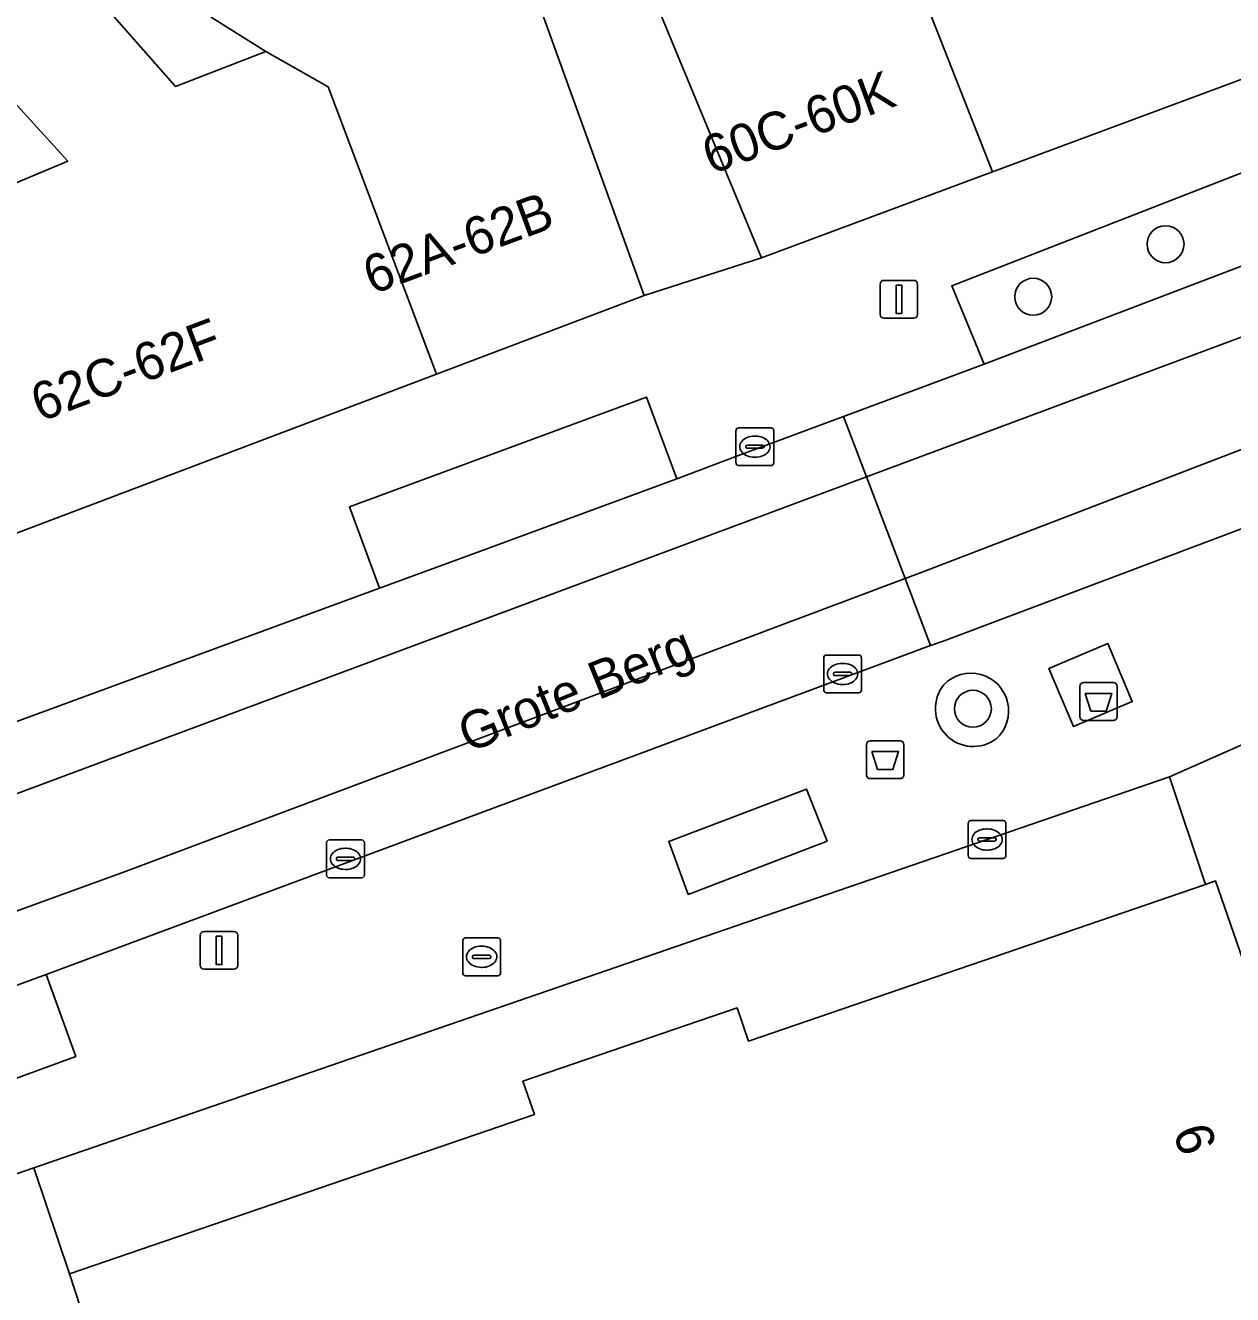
# Model space of a CAD drawing. Extents: x 160663 to 161506, y 382245 to 383291.
# Drawn here: x 161109.73 to 161141.68, y 382936.36 to 382969.94 of the extents above; entities that cross this region are included whole.
import ezdxf

# ---------------------------------------------------------------- set-up
doc = ezdxf.new("R2010")
doc.units = 0
for name, color, linetype in [('IMGEO_Afval_apart_plaats', 7, 'Continuous'), ('IMGEO_Afvalbak', 7, 'Continuous'), ('IMGEO_Boom', 7, 'Continuous'), ('IMGEO_Brandkraan', 7, 'Continuous'), ('IMGEO_Erf', 7, 'Continuous'), ('IMGEO_Groenvoorziening', 7, 'Continuous'), ('IMGEO_Kolk', 7, 'Continuous'), ('IMGEO_Lichtmast', 7, 'Continuous'), ('IMGEO_Openbare_ruimte_label', 7, 'Continuous'), ('IMGEO_Pand', 7, 'Continuous'), ('IMGEO_Pand_nummerreeks', 7, 'Continuous'), ('IMGEO_Rijbaan_lokaal_gesloten', 7, 'Continuous'), ('IMGEO_Voetpad_gesloten', 7, 'Continuous'), ('IMGEO_Voetpad_open', 7, 'Continuous')]:
    doc.layers.add(name, color=color, linetype=linetype)

msp = doc.modelspace()

# ---------------------------------------------------------------- linework, layer by layer
at = {"layer": 'IMGEO_Afval_apart_plaats'}
for p, q in [((161137.732, 382952.553), (161138.522, 382952.553)), ((161138.522, 382952.553), (161137.732, 382952.553)), ((161137.632, 382951.653), (161137.632, 382952.453)), ((161137.632, 382952.453), (161137.632, 382951.653)), ((161138.622, 382952.453), (161138.622, 382951.653)), ((161138.622, 382951.653), (161138.622, 382952.453)), ((161138.522, 382951.553), (161137.732, 382951.553)), ((161137.732, 382951.553), (161138.522, 382951.553))]:
    msp.add_line(p, q, dxfattribs=at)
msp.add_lwpolyline([(161137.775, 382952.267), (161138.479, 382952.267), (161138.33, 382951.797), (161137.924, 382951.797), (161137.775, 382952.267)], dxfattribs=at)
for centre, start, end in [((161137.732, 382952.453), 90, 180), ((161137.732, 382952.453), 90, 180), ((161138.522, 382952.453), 0, 90), ((161138.522, 382952.453), 360, 90), ((161137.732, 382951.653), 180, 270), ((161137.732, 382951.653), 180, 270), ((161138.522, 382951.653), 270, 0), ((161138.522, 382951.653), 270, 0)]:
    msp.add_arc(centre, 0.1, start, end, dxfattribs=at)
at = {"layer": 'IMGEO_Afvalbak'}
for p, q in [((161131.988, 382950.111), (161131.988, 382950.911)), ((161131.988, 382950.911), (161131.988, 382950.111)), ((161132.088, 382951.011), (161132.878, 382951.011)), ((161132.878, 382951.011), (161132.088, 382951.011)), ((161132.978, 382950.911), (161132.978, 382950.111)), ((161132.978, 382950.111), (161132.978, 382950.911)), ((161132.878, 382950.011), (161132.088, 382950.011)), ((161132.088, 382950.011), (161132.878, 382950.011))]:
    msp.add_line(p, q, dxfattribs=at)
msp.add_lwpolyline([(161132.131, 382950.725), (161132.835, 382950.725), (161132.686, 382950.255), (161132.28, 382950.255), (161132.131, 382950.725)], dxfattribs=at)
for centre, start, end in [((161132.088, 382950.911), 90, 180), ((161132.088, 382950.911), 90, 180), ((161132.878, 382950.911), 0, 90), ((161132.878, 382950.911), 360, 90), ((161132.088, 382950.111), 180, 270), ((161132.088, 382950.111), 180, 270), ((161132.878, 382950.111), 270, 0), ((161132.878, 382950.111), 270, 0)]:
    msp.add_arc(centre, 0.1, start, end, dxfattribs=at)
at = {"layer": 'IMGEO_Boom'}
for centre in [(161139.9, 382964.151), (161136.399, 382962.762), (161134.803, 382951.861)]:
    msp.add_circle(centre, 0.489, dxfattribs=at)
at = {"layer": 'IMGEO_Brandkraan'}
for p, q in [((161121.38, 382945.798), (161122.232, 382945.798)), ((161121.305, 382944.872), (161121.305, 382945.724)), ((161121.793, 382945.578), (161121.818, 382945.578)), ((161122.306, 382945.724), (161122.306, 382944.872)), ((161121.564, 382945.292), (161121.564, 382945.304)), ((161122.002, 382945.255), (161121.604, 382945.255)), ((161121.607, 382945.341), (161122.005, 382945.341)), ((161122.048, 382945.304), (161122.048, 382945.292)), ((161122.232, 382944.798), (161121.38, 382944.798)), ((161121.816, 382945.018), (161121.791, 382945.018))]:
    msp.add_line(p, q, dxfattribs=at)
for points in [[(161121.38, 382945.798), (161122.232, 382945.798)], [(161121.305, 382944.872), (161121.305, 382945.724)], [(161122.306, 382945.724), (161122.306, 382944.872)], [(161122.232, 382944.798), (161121.38, 382944.798)]]:
    msp.add_lwpolyline(points, dxfattribs=at)
for centre, radius, start, end in [((161121.382, 382945.722), 0.0765, 91.552, 178.448), ((161121.382, 382945.722), 0.0765, 91.552, 178.448), ((161122.23, 382945.722), 0.0765, 1.552, 88.448), ((161122.23, 382945.722), 0.0765, 1.552, 88.448), ((161121.604, 382945.301), 0.0403, 85.8775, 175.7526), ((161121.601, 382945.291), 0.0366, 178.938, 274.7102), ((161122.005, 382945.298), 0.043, 264.8664, 352.4533), ((161122.009, 382945.303), 0.0386, 1.7309, 96.639), ((161121.382, 382944.874), 0.0765, 181.552, 268.448), ((161121.382, 382944.874), 0.0765, 181.552, 268.448), ((161122.23, 382944.874), 0.0765, 271.552, 358.448), ((161122.23, 382944.874), 0.0765, 271.552, 358.448)]:
    msp.add_arc(centre, radius, start, end, dxfattribs=at)
for centre, major_axis, ratio, start_param, end_param in [((161121.792, 382945.298), (-0.387, 0.002), 0.722429, 4.712389, 7.853982), ((161121.817, 382945.298), (-0.39, 0.002), 0.717154, 1.570796, 4.712389)]:
    msp.add_ellipse(centre, major_axis=major_axis, ratio=ratio, start_param=start_param, end_param=end_param, dxfattribs=at)
at = {"layer": 'IMGEO_Erf'}
for points in [[(161123.369, 382970.359), (161126.109, 382962.795), (161129.211, 382963.795), (161127.298, 382968.415), (161122.938, 382978.941)], [(161110.247, 382972.258), (161113.708, 382968.321), (161116.095, 382969.253), (161114.672, 382970.145)], [(161107.732, 382965.041), (161110.852, 382966.351), (161107.621, 382969.898)]]:
    msp.add_lwpolyline(points, dxfattribs=at)
at = {"layer": 'IMGEO_Groenvoorziening'}
for points in [[(161147.667, 382965.769), (161146.804, 382967.946), (161134.242, 382963.047), (161135.104, 382960.976)], [(161126.169, 382960.107), (161121.008, 382958.201), (161118.308, 382957.204), (161119.104, 382955.049), (161121.778, 382956.03), (161126.973, 382957.945)], [(161110.287, 382944.833), (161106.36, 382943.391), (161102.099, 382941.861), (161102.869, 382939.677), (161107.347, 382941.305), (161111.066, 382942.663)]]:
    msp.add_lwpolyline(points, close=True, dxfattribs=at)
for centre, radius, start, end in [((161134.752, 382951.805), 0.996, 312.027, 136.0999), ((161134.813, 382951.863), 1.002, 140.8913, 307.2356)]:
    msp.add_arc(centre, radius, start, end, dxfattribs=at)
at = {"layer": 'IMGEO_Kolk'}
for p, q in [((161128.535, 382958.368), (161128.535, 382959.22)), ((161128.61, 382959.294), (161129.462, 382959.294)), ((161129.536, 382959.22), (161129.536, 382958.368)), ((161129.023, 382959.074), (161129.048, 382959.074)), ((161128.794, 382958.788), (161128.794, 382958.8)), ((161129.232, 382958.751), (161128.834, 382958.751)), ((161128.837, 382958.837), (161129.235, 382958.837)), ((161129.046, 382958.514), (161129.021, 382958.514)), ((161129.278, 382958.8), (161129.278, 382958.788)), ((161129.462, 382958.294), (161128.61, 382958.294)), ((161130.855, 382952.356), (161130.855, 382953.208)), ((161130.93, 382953.282), (161131.782, 382953.282)), ((161131.856, 382953.208), (161131.856, 382952.356)), ((161131.157, 382952.825), (161131.555, 382952.825)), ((161131.343, 382953.062), (161131.368, 382953.062)), ((161131.114, 382952.776), (161131.114, 382952.788)), ((161131.552, 382952.739), (161131.154, 382952.739)), ((161131.366, 382952.502), (161131.341, 382952.502)), ((161131.598, 382952.788), (161131.598, 382952.776)), ((161131.782, 382952.282), (161130.93, 382952.282)), ((161134.677, 382947.975), (161134.677, 382948.827)), ((161134.752, 382948.901), (161135.604, 382948.901)), ((161135.678, 382948.827), (161135.678, 382947.975)), ((161134.979, 382948.444), (161135.377, 382948.444)), ((161135.165, 382948.681), (161135.19, 382948.681)), ((161117.702, 382947.463), (161117.702, 382948.315)), ((161117.777, 382948.389), (161118.629, 382948.389)), ((161118.19, 382948.169), (161118.215, 382948.169)), ((161118.703, 382948.315), (161118.703, 382947.463)), ((161134.936, 382948.395), (161134.936, 382948.407)), ((161135.374, 382948.358), (161134.976, 382948.358)), ((161135.188, 382948.121), (161135.163, 382948.121)), ((161135.42, 382948.407), (161135.42, 382948.395)), ((161117.961, 382947.883), (161117.961, 382947.895)), ((161118.399, 382947.846), (161118.001, 382947.846)), ((161118.004, 382947.932), (161118.402, 382947.932)), ((161118.445, 382947.895), (161118.445, 382947.883)), ((161135.604, 382947.901), (161134.752, 382947.901)), ((161118.213, 382947.609), (161118.188, 382947.609)), ((161118.629, 382947.389), (161117.777, 382947.389))]:
    msp.add_line(p, q, dxfattribs=at)
for points in [[(161128.535, 382958.368), (161128.535, 382959.22)], [(161128.61, 382959.294), (161129.462, 382959.294)], [(161129.536, 382959.22), (161129.536, 382958.368)], [(161129.462, 382958.294), (161128.61, 382958.294)], [(161130.855, 382952.356), (161130.855, 382953.208)], [(161130.93, 382953.282), (161131.782, 382953.282)], [(161131.856, 382953.208), (161131.856, 382952.356)], [(161131.782, 382952.282), (161130.93, 382952.282)], [(161134.677, 382947.975), (161134.677, 382948.827)], [(161134.752, 382948.901), (161135.604, 382948.901)], [(161135.678, 382948.827), (161135.678, 382947.975)], [(161117.702, 382947.463), (161117.702, 382948.315)], [(161117.777, 382948.389), (161118.629, 382948.389)], [(161118.703, 382948.315), (161118.703, 382947.463)], [(161135.604, 382947.901), (161134.752, 382947.901)], [(161118.629, 382947.389), (161117.777, 382947.389)]]:
    msp.add_lwpolyline(points, dxfattribs=at)
for centre, radius, start, end in [((161128.612, 382959.218), 0.0765, 91.552, 178.448), ((161128.612, 382959.218), 0.0765, 91.552, 178.448), ((161129.46, 382959.218), 0.0765, 1.552, 88.448), ((161129.46, 382959.218), 0.0765, 1.552, 88.448), ((161128.834, 382958.797), 0.0403, 85.8775, 175.7526), ((161128.831, 382958.787), 0.0366, 178.938, 274.7102), ((161129.235, 382958.794), 0.043, 264.8664, 352.4533), ((161129.239, 382958.799), 0.0386, 1.7309, 96.639), ((161128.612, 382958.37), 0.0765, 181.552, 268.448), ((161128.612, 382958.37), 0.0765, 181.552, 268.448), ((161129.46, 382958.37), 0.0765, 271.552, 358.448), ((161129.46, 382958.37), 0.0765, 271.552, 358.448), ((161130.932, 382953.206), 0.0765, 91.552, 178.448), ((161130.932, 382953.206), 0.0765, 91.552, 178.448), ((161131.78, 382953.206), 0.0765, 1.552, 88.448), ((161131.78, 382953.206), 0.0765, 1.552, 88.448), ((161131.154, 382952.785), 0.0403, 85.8775, 175.7526), ((161131.559, 382952.787), 0.0386, 1.7309, 96.639), ((161131.151, 382952.775), 0.0366, 178.938, 274.7102), ((161131.555, 382952.782), 0.043, 264.8664, 352.4533), ((161130.932, 382952.358), 0.0765, 181.552, 268.448), ((161130.932, 382952.358), 0.0765, 181.552, 268.448), ((161131.78, 382952.358), 0.0765, 271.552, 358.448), ((161131.78, 382952.358), 0.0765, 271.552, 358.448), ((161134.754, 382948.825), 0.0765, 91.552, 178.448), ((161134.754, 382948.825), 0.0765, 91.552, 178.448), ((161135.602, 382948.825), 0.0765, 1.552, 88.448), ((161135.602, 382948.825), 0.0765, 1.552, 88.448), ((161134.976, 382948.404), 0.0403, 85.8775, 175.7526), ((161135.381, 382948.406), 0.0386, 1.7309, 96.639), ((161117.779, 382948.313), 0.0765, 91.552, 178.448), ((161117.779, 382948.313), 0.0765, 91.552, 178.448), ((161118.627, 382948.313), 0.0765, 1.552, 88.448), ((161118.627, 382948.313), 0.0765, 1.552, 88.448), ((161134.973, 382948.394), 0.0366, 178.938, 274.7102), ((161135.377, 382948.401), 0.043, 264.8664, 352.4533), ((161118.001, 382947.892), 0.0403, 85.8775, 175.7526), ((161117.998, 382947.882), 0.0366, 178.938, 274.7102), ((161118.402, 382947.889), 0.043, 264.8664, 352.4533), ((161118.406, 382947.894), 0.0386, 1.7309, 96.639), ((161134.754, 382947.977), 0.0765, 181.552, 268.448), ((161134.754, 382947.977), 0.0765, 181.552, 268.448), ((161135.602, 382947.977), 0.0765, 271.552, 358.448), ((161135.602, 382947.977), 0.0765, 271.552, 358.448), ((161117.779, 382947.465), 0.0765, 181.552, 268.448), ((161117.779, 382947.465), 0.0765, 181.552, 268.448), ((161118.627, 382947.465), 0.0765, 271.552, 358.448), ((161118.627, 382947.465), 0.0765, 271.552, 358.448)]:
    msp.add_arc(centre, radius, start, end, dxfattribs=at)
for centre, major_axis, ratio, start_param, end_param in [((161129.022, 382958.794), (-0.387, 0.002), 0.722429, 4.712389, 7.853982), ((161129.047, 382958.794), (-0.39, 0.002), 0.717154, 1.570796, 4.712389), ((161131.342, 382952.782), (-0.387, 0.002), 0.722429, 4.712389, 7.853982), ((161131.367, 382952.782), (-0.39, 0.002), 0.717154, 1.570796, 4.712389), ((161135.164, 382948.401), (-0.387, 0.002), 0.722429, 4.712389, 7.853982), ((161135.189, 382948.401), (-0.39, 0.002), 0.717154, 1.570796, 4.712389), ((161118.189, 382947.889), (-0.387, 0.002), 0.722429, 4.712389, 7.853982), ((161118.214, 382947.889), (-0.39, 0.002), 0.717154, 1.570796, 4.712389)]:
    msp.add_ellipse(centre, major_axis=major_axis, ratio=ratio, start_param=start_param, end_param=end_param, dxfattribs=at)
at = {"layer": 'IMGEO_Lichtmast'}
for p, q in [((161132.349, 382962.295), (161132.349, 382963.095)), ((161132.349, 382963.095), (161132.349, 382962.295)), ((161132.449, 382963.195), (161133.239, 382963.195)), ((161133.239, 382963.195), (161132.449, 382963.195)), ((161133.339, 382963.095), (161133.339, 382962.295)), ((161133.339, 382962.295), (161133.339, 382963.095)), ((161133.239, 382962.195), (161132.449, 382962.195)), ((161132.449, 382962.195), (161133.239, 382962.195)), ((161114.362, 382945.068), (161114.362, 382945.868)), ((161114.362, 382945.868), (161114.362, 382945.068)), ((161114.462, 382945.968), (161115.252, 382945.968)), ((161115.252, 382945.968), (161114.462, 382945.968)), ((161115.352, 382945.868), (161115.352, 382945.068)), ((161115.352, 382945.068), (161115.352, 382945.868)), ((161115.252, 382944.968), (161114.462, 382944.968)), ((161114.462, 382944.968), (161115.252, 382944.968))]:
    msp.add_line(p, q, dxfattribs=at)
for points in [[(161132.769, 382963.07), (161132.919, 382963.07), (161132.919, 382962.32), (161132.769, 382962.32), (161132.769, 382963.07)], [(161114.782, 382945.843), (161114.932, 382945.843), (161114.932, 382945.093), (161114.782, 382945.093), (161114.782, 382945.843)]]:
    msp.add_lwpolyline(points, dxfattribs=at)
for centre, start, end in [((161132.449, 382963.095), 90, 180), ((161132.449, 382963.095), 90, 180), ((161133.239, 382963.095), 0, 90), ((161133.239, 382963.095), 360, 90), ((161132.449, 382962.295), 180, 270), ((161132.449, 382962.295), 180, 270), ((161133.239, 382962.295), 270, 0), ((161133.239, 382962.295), 270, 0), ((161114.462, 382945.868), 90, 180), ((161114.462, 382945.868), 90, 180), ((161115.252, 382945.868), 0, 90), ((161115.252, 382945.868), 360, 90), ((161114.462, 382945.068), 180, 270), ((161114.462, 382945.068), 180, 270), ((161115.252, 382945.068), 270, 0), ((161115.252, 382945.068), 270, 0)]:
    msp.add_arc(centre, 0.1, start, end, dxfattribs=at)
at = {"layer": 'IMGEO_Pand'}
for points in [[(161135.325, 382966.07), (161149.636, 382971.394), (161150.064, 382971.569), (161142.845, 382980.928), (161139.695, 382984.677), (161127.727, 382998.923), (161120.931, 382988.401), (161121.32, 382988.191), (161124.191, 382984.784), (161131.708, 382975.266)], [(161124.191, 382984.784), (161110.303, 382978.748), (161113.83, 382976.389), (161120.744, 382979.272), (161121.184, 382978.209), (161122.938, 382978.941), (161127.298, 382968.415), (161129.211, 382963.795), (161135.325, 382966.07), (161131.708, 382975.266)], [(161120.614, 382960.716), (161126.109, 382962.795), (161123.369, 382970.359), (161117.359, 382974.264), (161114.832, 382975.786), (161112.557, 382972.008), (161114.672, 382970.145), (161116.095, 382969.253), (161117.746, 382968.316)], [(161117.746, 382968.316), (161116.095, 382969.253), (161113.708, 382968.321), (161110.247, 382972.258), (161107.621, 382969.898), (161110.852, 382966.351), (161107.732, 382965.041), (161105.832, 382970.116), (161102.151, 382968.811), (161104.537, 382963.884), (161108.324, 382956.065), (161120.614, 382960.716)], [(161110.9, 382936.908), (161109.961, 382939.715), (161102.286, 382937.062), (161107.951, 382921.591), (161108.095, 382921.199), (161111.58, 382922.47), (161111.096, 382923.797), (161109.908, 382927.327), (161113.63, 382928.589), (161113.584, 382928.696)]]:
    msp.add_lwpolyline(points, close=True, dxfattribs=at)
msp.add_lwpolyline([(161143.563, 382913.86), (161143.599, 382914.302), (161137.846, 382914.754), (161136.339, 382932.226), (161145.362, 382935.353), (161141.221, 382947.303), (161140.962, 382947.214), (161128.866, 382943.067), (161128.565, 382943.947), (161122.899, 382942.005), (161123.2, 382941.125), (161110.9, 382936.908), (161113.584, 382928.696), (161113.63, 382928.589), (161113.797, 382928.646), (161115.023, 382925.049), (161122.092, 382927.458), (161123.613, 382910.32)], dxfattribs=at)
at = {"layer": 'IMGEO_Rijbaan_lokaal_gesloten'}
for points in [[(161148.412, 382964.113), (161156.081, 382967.198), (161155.41, 382968.873), (161147.667, 382965.769), (161135.104, 382960.976), (161131.383, 382959.595), (161131.99, 382957.995)], [(161157.124, 382964.597), (161156.081, 382967.198), (161148.412, 382964.113), (161131.99, 382957.995), (161133.011, 382955.303), (161133.457, 382955.47), (161154.805, 382963.673)], [(161157.832, 382962.832), (161157.124, 382964.597), (161154.805, 382963.673), (161133.457, 382955.47), (161133.011, 382955.303), (161133.682, 382953.531), (161134.046, 382953.655), (161146.471, 382958.343)]]:
    msp.add_lwpolyline(points, close=True, dxfattribs=at)
for points in [[(161080.422, 382939.64), (161098.89, 382945.662), (161131.99, 382957.995), (161131.383, 382959.595), (161128.533, 382958.538), (161126.973, 382957.945), (161121.778, 382956.03), (161119.104, 382955.049), (161107.841, 382950.917), (161105.16, 382949.934), (161099.951, 382948.027), (161096.277, 382946.705), (161078.659, 382940.942)], [(161100.365, 382943.182), (161101.826, 382943.714), (161112.429, 382947.575), (161133.011, 382955.303), (161131.99, 382957.995), (161098.89, 382945.662), (161080.422, 382939.64)], [(161102.099, 382941.861), (161106.36, 382943.391), (161110.287, 382944.833), (161133.682, 382953.531), (161133.011, 382955.303), (161112.429, 382947.575), (161101.826, 382943.714), (161100.365, 382943.182)]]:
    msp.add_lwpolyline(points, dxfattribs=at)
at = {"layer": 'IMGEO_Voetpad_gesloten'}
for points in [[(161137.463, 382951.391), (161139.018, 382952.053), (161138.375, 382953.591), (161136.814, 382952.928)], [(161130.946, 382948.354), (161130.404, 382949.737), (161126.758, 382948.352), (161127.27, 382946.95)]]:
    msp.add_lwpolyline(points, close=True, dxfattribs=at)
at = {"layer": 'IMGEO_Voetpad_open'}
for points in [[(161162.228, 382976.56), (161157.171, 382974.486), (161157.525, 382973.62), (161150.92, 382970.921), (161150.57, 382971.777), (161150.064, 382971.569), (161149.636, 382971.394), (161135.325, 382966.07), (161129.211, 382963.795), (161126.109, 382962.795), (161120.614, 382960.716), (161108.324, 382956.065), (161108.16, 382956.003), (161097.669, 382952.41), (161094.221, 382951.27), (161089.965, 382949.829), (161089.012, 382949.506), (161082.437, 382947.335), (161075.318, 382944.985)], [(161078.659, 382940.942), (161096.277, 382946.705), (161099.951, 382948.027), (161099.178, 382950.212), (161104.384, 382952.098), (161107.076, 382953.073), (161107.841, 382950.917), (161119.104, 382955.049), (161118.308, 382957.204), (161121.008, 382958.201), (161126.169, 382960.107), (161126.973, 382957.945), (161128.533, 382958.538), (161131.383, 382959.595), (161135.104, 382960.976), (161134.242, 382963.047), (161146.804, 382967.946), (161147.667, 382965.769), (161155.41, 382968.873), (161159.386, 382970.467)], [(161158.309, 382963.049), (161157.832, 382962.832), (161146.471, 382958.343), (161134.046, 382953.655), (161133.682, 382953.531), (161110.287, 382944.833), (161111.066, 382942.663), (161107.347, 382941.305), (161102.869, 382939.677), (161102.099, 382941.861), (161098.877, 382940.719), (161096.497, 382939.89), (161097.266, 382937.711)], [(161078.085, 382929.442), (161084.715, 382931.203), (161084.781, 382931.011), (161084.811, 382931.021), (161092.342, 382933.624), (161099.776, 382936.194), (161102.286, 382937.062), (161109.961, 382939.715), (161126.951, 382945.57), (161130.667, 382946.848), (161140.009, 382950.063), (161159.988, 382958.892)], [(161159.988, 382958.892), (161140.009, 382950.063), (161140.962, 382947.214), (161141.221, 382947.303), (161145.362, 382935.353), (161143.599, 382914.302), (161143.563, 382913.86), (161144.031, 382913.8), (161141.51, 382882.824), (161141.018, 382882.863), (161140.981, 382882.422), (161140.996, 382882.421), (161140.806, 382880.615), (161140.449, 382880.099), (161140.784, 382879.832), (161139.714, 382878.392), (161139.357, 382878.667), (161136.742, 382875.246), (161118.078, 382850.867), (161121.308, 382848.368), (161133.417, 382864.187)]]:
    msp.add_lwpolyline(points, dxfattribs=at)
for points in [[(161139.018, 382952.053), (161137.463, 382951.391), (161136.814, 382952.928), (161138.375, 382953.591)], [(161128.565, 382943.947), (161128.866, 382943.067), (161140.962, 382947.214), (161140.009, 382950.063), (161130.667, 382946.848), (161126.951, 382945.57), (161109.961, 382939.715), (161110.9, 382936.908), (161123.2, 382941.125), (161122.899, 382942.005)], [(161130.946, 382948.354), (161127.27, 382946.95), (161126.758, 382948.352), (161130.404, 382949.737)]]:
    msp.add_lwpolyline(points, close=True, dxfattribs=at)
for centre, radius, start, end in [((161134.752, 382951.805), 0.996, 312.027, 136.0999), ((161134.813, 382951.863), 1.002, 140.8913, 307.2356)]:
    msp.add_arc(centre, radius, start, end, dxfattribs=at)

# ---------------------------------------------------------------- texts
at = {"layer": 'IMGEO_Openbare_ruimte_label'}
msp.add_text('Grote Berg', height=1, rotation=22.1526, dxfattribs=at).set_placement((161121.45, 382950.684))
at = {"layer": 'IMGEO_Pand_nummerreeks'}
for s, rotation, p in [('60C-60K', 20.4088, (161127.884, 382965.99)), ('62A-62B', 20.3441, (161118.91, 382962.814)), ('62C-62F', 20.7296, (161110.127, 382959.443)), ('6', 288.6209, (161140.087, 382940.674))]:
    msp.add_text(s, height=1, rotation=rotation, dxfattribs=at).set_placement(p)

doc.saveas('drawing.dxf')
